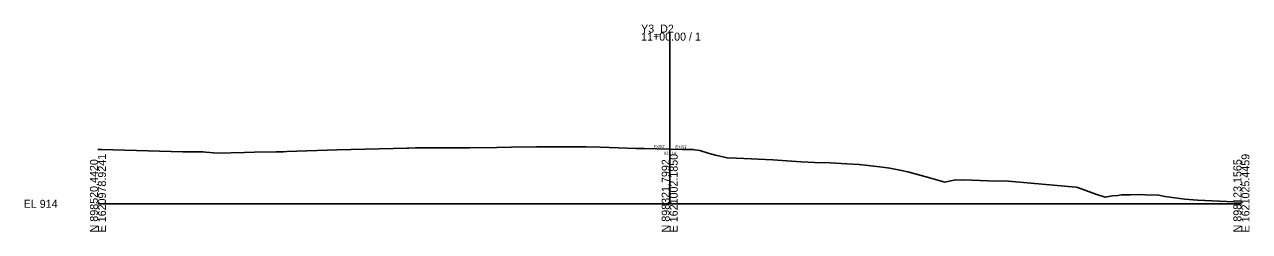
# Model space of a CAD drawing. Extents: x 162 to 3869, y 3 to 5514.
# Drawn here: x 3440.3 to 3868.9, y 2869.4 to 2941.8 of the extents above; entities that cross this region are included whole.
import ezdxf

# ---------------------------------------------------------------- set-up
doc = ezdxf.new("R2010")
doc.units = 0
for name, color, linetype in [('Exist Cross Section Cell', 7, 'Continuous'), ('Exist XS Center Line Elevation Label', 7, 'Continuous'), ('Exist XS Ground Line', 7, 'Continuous'), ('Old_Level_63', 7, 'Continuous'), ('Prop XS SE Text', 7, 'Continuous')]:
    doc.layers.add(name, color=color, linetype=linetype)

msp = doc.modelspace()

# ---------------------------------------------------------------- linework, layer by layer
at = {"layer": 'Exist Cross Section Cell'}
for p, q in [((3666.03, 2879.08), (3666.03, 2939)), ((3466.03, 2879.08), (3666.03, 2879.08)), ((3666.03, 2879.08), (3866.03, 2879.08))]:
    msp.add_line(p, q, dxfattribs=at)
at = {"layer": 'Exist XS Ground Line'}
msp.add_lwpolyline([(3466.03, 2898.13), (3467.28, 2898.14), (3495.72, 2897.26), (3498.43, 2897.31), (3502.67, 2897.32), (3503.72, 2897.2), (3507.84, 2896.76), (3517.24, 2897.04), (3520.84, 2897.15), (3528.33, 2897.27), (3530.91, 2897.33), (3532.12, 2897.35), (3549.66, 2897.94), (3574.14, 2898.57), (3574.47, 2898.57), (3574.8, 2898.58), (3577.09, 2898.64), (3589.16, 2898.68), (3596.15, 2898.65), (3605.53, 2898.79), (3610.74, 2898.89), (3619.41, 2899.05), (3621.8, 2899.04), (3630.47, 2899.01), (3636.81, 2898.99), (3641.66, 2898.9), (3647.97, 2898.64), (3654.29, 2898.49), (3657.1, 2898.43), (3666.03, 2898.22), (3670.51, 2898.11), (3673.24, 2898.08), (3674.22, 2898.07), (3674.8, 2897.96), (3676.57, 2897.71), (3679.46, 2896.86), (3680.3, 2896.57), (3682.05, 2896.06), (3686.1, 2895.15), (3689.37, 2895.01), (3702.08, 2894.49), (3708.59, 2893.98), (3712.14, 2893.8), (3716.64, 2893.59), (3722.21, 2893.37), (3728.04, 2893.02), (3732.28, 2892.84), (3739.52, 2892.01), (3742.99, 2891.5), (3747.09, 2890.74), (3749.32, 2890.33), (3756.53, 2888.31), (3762.3, 2886.67), (3763.81, 2886.96), (3766.1, 2887.49), (3768.09, 2887.4), (3768.94, 2887.42), (3777.28, 2887.16), (3784.56, 2886.98), (3792.42, 2886.3), (3804.23, 2885.26), (3805.41, 2885.16), (3808.25, 2884.85), (3808.71, 2884.8), (3815.46, 2882.29), (3818.35, 2881.46), (3820.21, 2881.76), (3820.95, 2881.85), (3822.76, 2882.04), (3824.09, 2882.17), (3826.19, 2882.24), (3827.19, 2882.25), (3830.3, 2882.29), (3832.51, 2882.25), (3837.09, 2882.12), (3839.3, 2881.68), (3846.26, 2880.69), (3850.7, 2880.37), (3855.77, 2880.07), (3866.03, 2879.69)], dxfattribs=at)
at = {"layer": 'Old_Level_63'}
msp.add_line((3666.03, 2898.22), (3666.03, 2900.99), dxfattribs=at)

# ---------------------------------------------------------------- texts
at = {"layer": 'Exist Cross Section Cell'}
for s, p in [('Y3_D2', (3656.03, 2939)), ('11+00.00 / 1', (3656.03, 2936.2)), ('EL 914', (3440.03, 2877.68))]:
    msp.add_text(s, height=2.8, dxfattribs=at).set_placement(p)
for s, p in [('N 898520.4420', (3466.03, 2869.08)), ('E 1620978.9241', (3468.83, 2869.08)), ('N 898321.7992', (3666.03, 2869.08)), ('E 1621002.1850', (3668.83, 2869.08)), ('N 898123.1565', (3866.03, 2869.08)), ('E 1621025.4459', (3868.83, 2869.08))]:
    msp.add_text(s, height=2.8, rotation=90, dxfattribs=at).set_placement(p)
at = {"layer": 'Exist XS Center Line Elevation Label'}
msp.add_text('933.14', height=1, dxfattribs=at).set_placement((3664.01, 2896.3))
at = {"layer": 'Prop XS SE Text'}
for rotation, p in [(1.1458, (3660.4, 2898.52)), (358.8542, (3668.05, 2898.49))]:
    msp.add_text('EXIST', height=1, rotation=rotation, dxfattribs=at).set_placement(p)

doc.saveas('drawing.dxf')
